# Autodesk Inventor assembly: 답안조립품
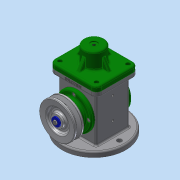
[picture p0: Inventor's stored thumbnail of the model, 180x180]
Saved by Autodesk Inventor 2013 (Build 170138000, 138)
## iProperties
Created: 2018-10
Part Number: 답안조립품
Document SubType Name: Assembly
Designer: dgall
Author: dgall
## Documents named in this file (18)
- C:\Users\dgall\Desktop\481007V1070\답안조립품.iam
- C:\Users\dgall\Desktop\481007V1070\본체.ipt
- C:\Users\dgall\Desktop\481007V1070\E-링.ipt
- C:\Users\dgall\Desktop\481007V1070\V-벨트풀리.ipt
- C:\Users\dgall\Desktop\481007V1070\덮개.ipt
- C:\Users\dgall\Desktop\481007V1070\뒤커버.ipt
- C:\Users\dgall\Desktop\481007V1070\링크.ipt
- C:\Users\dgall\Desktop\481007V1070\베어링 17 x 40 x 12.ipt
- C:\Users\dgall\Desktop\481007V1070\볼트 M4 x 8.ipt
- C:\Users\dgall\Desktop\481007V1070\볼트 M4 x 10.ipt
- C:\Users\dgall\Desktop\481007V1070\슬라이더.ipt
- C:\Users\dgall\Desktop\481007V1070\앞커버.ipt
- C:\Users\dgall\Desktop\481007V1070\오일 실 17 30 8.ipt
- C:\Users\dgall\Desktop\481007V1070\와셔 4x16.ipt
- C:\Users\dgall\Desktop\481007V1070\클레비스 핀 6 x 22.ipt
- 클레비스 핀 6 x 22.ipt
- C:\Users\dgall\Desktop\481007V1070\키 4 x 4 x 12.ipt
- C:\Users\dgall\Desktop\481007V1070\편심축.ipt
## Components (2 placed, 2 different names)
1. E-링:1
2. V-벨트풀리:1
